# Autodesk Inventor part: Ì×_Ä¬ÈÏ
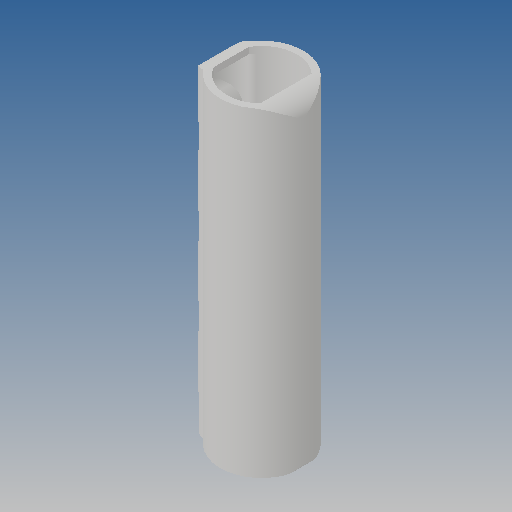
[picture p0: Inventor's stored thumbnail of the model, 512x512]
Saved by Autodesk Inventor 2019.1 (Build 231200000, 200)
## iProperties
Created: 2012-10
Part Number: Ì×_Ä¬ÈÏ
Material: Ogólny
Document SubType Name: Modeling
Designer: CADENGINEERING4
Density: 1 g/cm^3
Appearance: Domyślna
Author: CADENGINEERING4
Revision Number: ÈÎºÎ
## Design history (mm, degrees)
feature "NONE"
node "Bryła1"
